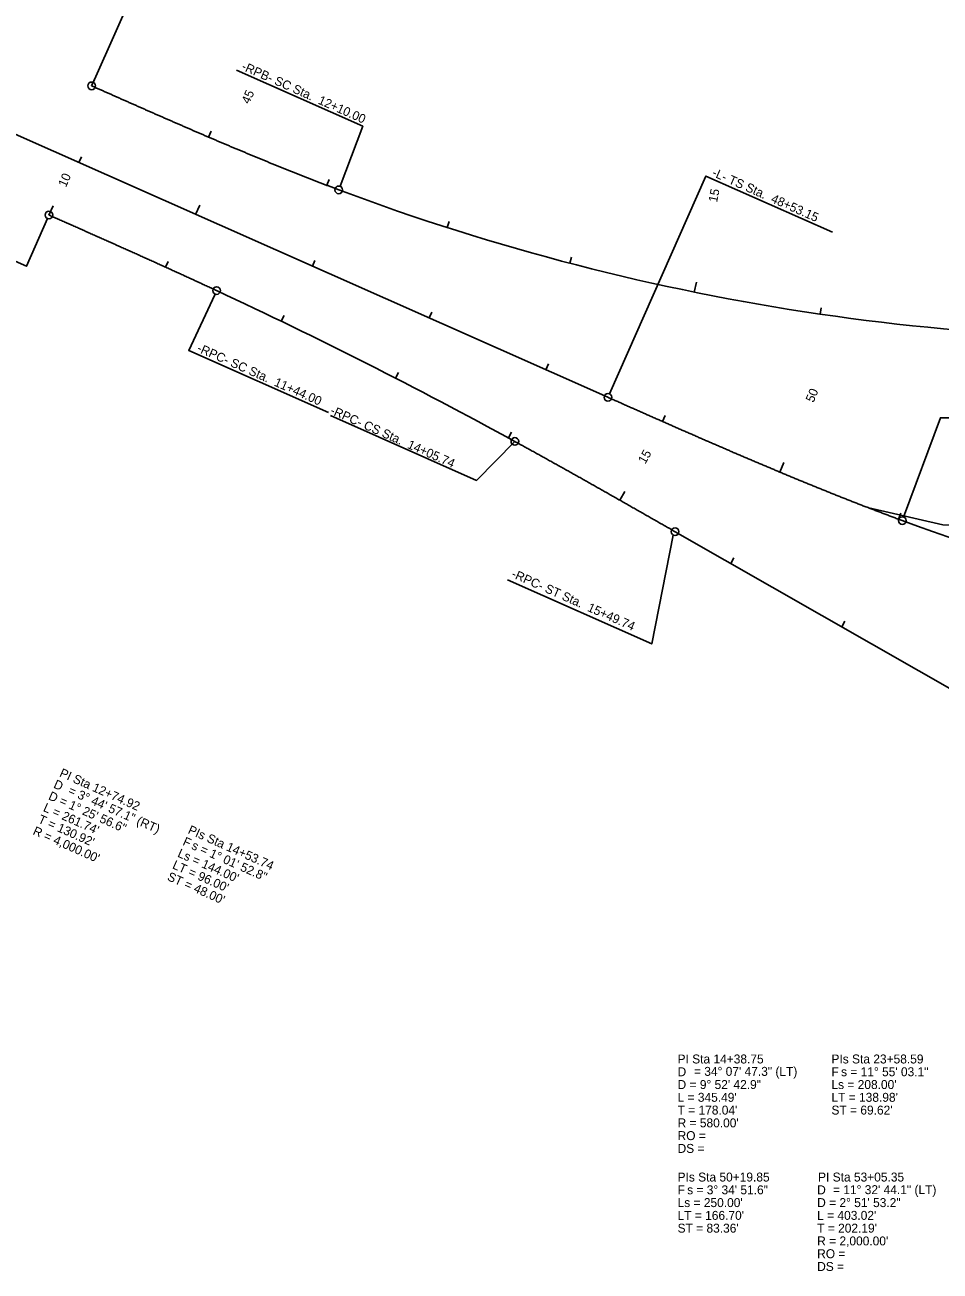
# Model space of a CAD drawing. Extents: x 1636713 to 1642783, y 841520 to 844371.
# Drawn here: x 1639901 to 1640618, y 841942 to 842918 of the extents above; entities that cross this region are included whole.
import ezdxf

# ---------------------------------------------------------------- set-up
doc = ezdxf.new("R2010")
doc.units = 0
for name, color, linetype in [('Prop Horizontal Alignment', 7, 'Continuous'), ('Prop Horizontal Alignment Curve and Spiral Data', 7, 'Continuous'), ('Prop Horizontal Alignment Station Label', 7, 'Continuous'), ('Prop Horizontal Alignment Tick Label', 7, 'Continuous'), ('Prop Horizontal Alignment Tick Large', 7, 'Continuous'), ('Prop Horizontal Alignment Tick Small', 7, 'Continuous')]:
    doc.layers.add(name, color=color, linetype=linetype)

msp = doc.modelspace()

# ---------------------------------------------------------------- linework, layer by layer
at = {"layer": 'Prop Horizontal Alignment'}
for p, q in [((1638900.9, 843272.49), (1640357.88, 842626.45)), ((1640410.49, 842521.24), (1640992.21, 842189.1)), ((1640410.49, 842521.24), (1640992.21, 842189.1))]:
    msp.add_line(p, q, dxfattribs=at)
for centre, radius, start, end in [((1640787.73, 844492.39), 1820, 249.39267, 273.94216), ((1638364.53, 839083.08), 4000, 61.30663, 65.05582), ((1638364.53, 839083.08), 4000, 61.30663, 65.05582), ((1641283.36, 844405.31), 2000, 249.66813, 261.21372)]:
    msp.add_arc(centre, radius, start, end, dxfattribs=at)
for points in [[(1639953.61, 842870.25), (1639956.21, 842869.1), (1639958.8, 842867.95), (1639961.4, 842866.8), (1639963.99, 842865.65), (1639966.58, 842864.5), (1639969.18, 842863.35), (1639971.77, 842862.2), (1639974.37, 842861.05), (1639976.96, 842859.9), (1639979.56, 842858.75), (1639982.15, 842857.61), (1639984.75, 842856.46), (1639987.35, 842855.31), (1639989.94, 842854.17), (1639992.54, 842853.02), (1639995.14, 842851.88), (1639997.73, 842850.74), (1640000.33, 842849.6), (1640002.93, 842848.45), (1640005.53, 842847.31), (1640008.13, 842846.18), (1640010.73, 842845.04), (1640013.33, 842843.9), (1640015.93, 842842.77), (1640018.53, 842841.63), (1640021.13, 842840.5), (1640023.74, 842839.37), (1640026.34, 842838.24), (1640028.94, 842837.11), (1640031.55, 842835.98), (1640034.15, 842834.86), (1640036.76, 842833.74), (1640039.37, 842832.62), (1640041.97, 842831.5), (1640044.58, 842830.38), (1640047.19, 842829.26), (1640049.8, 842828.15), (1640052.41, 842827.04), (1640055.03, 842825.93), (1640057.64, 842824.82), (1640060.25, 842823.71), (1640062.87, 842822.61), (1640065.48, 842821.51), (1640068.1, 842820.41), (1640070.72, 842819.32), (1640073.34, 842818.22), (1640075.95, 842817.13), (1640078.58, 842816.04), (1640081.2, 842814.96), (1640083.82, 842813.88), (1640086.44, 842812.79), (1640089.07, 842811.72), (1640091.7, 842810.64), (1640094.32, 842809.57), (1640096.95, 842808.5), (1640099.58, 842807.44), (1640102.22, 842806.37), (1640104.85, 842805.32), (1640107.48, 842804.26), (1640110.12, 842803.21), (1640112.75, 842802.16), (1640115.39, 842801.11), (1640118.03, 842800.07), (1640120.67, 842799.03), (1640123.31, 842797.99), (1640125.96, 842796.96), (1640128.6, 842795.93), (1640131.25, 842794.91), (1640133.9, 842793.89), (1640136.55, 842792.87), (1640139.2, 842791.86), (1640141.85, 842790.85), (1640144.5, 842789.85), (1640147.16, 842788.84)], [(1639920.18, 842769.12), (1639921.96, 842768.33), (1639923.74, 842767.54), (1639925.52, 842766.75), (1639927.3, 842765.96), (1639929.08, 842765.17), (1639930.86, 842764.38), (1639932.64, 842763.6), (1639934.41, 842762.81), (1639936.19, 842762.02), (1639937.97, 842761.23), (1639939.75, 842760.44), (1639941.53, 842759.65), (1639943.31, 842758.86), (1639945.09, 842758.07), (1639946.86, 842757.28), (1639948.64, 842756.49), (1639950.42, 842755.7), (1639952.2, 842754.91), (1639953.98, 842754.12), (1639955.75, 842753.33), (1639957.53, 842752.53), (1639959.31, 842751.74), (1639961.09, 842750.95), (1639962.87, 842750.16), (1639964.64, 842749.37), (1639966.42, 842748.57), (1639968.2, 842747.78), (1639969.97, 842746.99), (1639971.75, 842746.2), (1639973.53, 842745.4), (1639975.3, 842744.61), (1639977.08, 842743.81), (1639978.86, 842743.02), (1639980.63, 842742.22), (1639982.41, 842741.43), (1639984.18, 842740.63), (1639985.96, 842739.83), (1639987.73, 842739.04), (1639989.51, 842738.24), (1639991.28, 842737.44), (1639993.06, 842736.64), (1639994.83, 842735.84), (1639996.61, 842735.04), (1639998.38, 842734.25), (1640000.16, 842733.44), (1640001.93, 842732.64), (1640003.7, 842731.84), (1640005.48, 842731.04), (1640007.25, 842730.24), (1640009.02, 842729.43), (1640010.79, 842728.63), (1640012.56, 842727.83), (1640014.34, 842727.02), (1640016.11, 842726.22), (1640017.88, 842725.41), (1640019.65, 842724.6), (1640021.42, 842723.8), (1640023.19, 842722.99), (1640024.96, 842722.18), (1640026.73, 842721.37), (1640028.5, 842720.56), (1640030.27, 842719.75), (1640032.04, 842718.94), (1640033.81, 842718.13), (1640035.57, 842717.31), (1640037.34, 842716.5), (1640039.11, 842715.68), (1640040.87, 842714.87), (1640042.64, 842714.05), (1640044.41, 842713.24), (1640046.17, 842712.42), (1640047.94, 842711.6), (1640049.7, 842710.78), (1640051.47, 842709.96)], [(1639920.18, 842769.12), (1639921.96, 842768.33), (1639923.74, 842767.54), (1639925.52, 842766.75), (1639927.3, 842765.96), (1639929.08, 842765.17), (1639930.86, 842764.38), (1639932.64, 842763.6), (1639934.41, 842762.81), (1639936.19, 842762.02), (1639937.97, 842761.23), (1639939.75, 842760.44), (1639941.53, 842759.65), (1639943.31, 842758.86), (1639945.09, 842758.07), (1639946.86, 842757.28), (1639948.64, 842756.49), (1639950.42, 842755.7), (1639952.2, 842754.91), (1639953.98, 842754.12), (1639955.75, 842753.33), (1639957.53, 842752.53), (1639959.31, 842751.74), (1639961.09, 842750.95), (1639962.87, 842750.16), (1639964.64, 842749.37), (1639966.42, 842748.57), (1639968.2, 842747.78), (1639969.97, 842746.99), (1639971.75, 842746.2), (1639973.53, 842745.4), (1639975.3, 842744.61), (1639977.08, 842743.81), (1639978.86, 842743.02), (1639980.63, 842742.22), (1639982.41, 842741.43), (1639984.18, 842740.63), (1639985.96, 842739.83), (1639987.73, 842739.04), (1639989.51, 842738.24), (1639991.28, 842737.44), (1639993.06, 842736.64), (1639994.83, 842735.84), (1639996.61, 842735.04), (1639998.38, 842734.25), (1640000.16, 842733.44), (1640001.93, 842732.64), (1640003.7, 842731.84), (1640005.48, 842731.04), (1640007.25, 842730.24), (1640009.02, 842729.43), (1640010.79, 842728.63), (1640012.56, 842727.83), (1640014.34, 842727.02), (1640016.11, 842726.22), (1640017.88, 842725.41), (1640019.65, 842724.6), (1640021.42, 842723.8), (1640023.19, 842722.99), (1640024.96, 842722.18), (1640026.73, 842721.37), (1640028.5, 842720.56), (1640030.27, 842719.75), (1640032.04, 842718.94), (1640033.81, 842718.13), (1640035.57, 842717.31), (1640037.34, 842716.5), (1640039.11, 842715.68), (1640040.87, 842714.87), (1640042.64, 842714.05), (1640044.41, 842713.24), (1640046.17, 842712.42), (1640047.94, 842711.6), (1640049.7, 842710.78), (1640051.47, 842709.96)], [(1640357.88, 842626.45), (1640360.97, 842625.08), (1640364.06, 842623.71), (1640367.14, 842622.35), (1640370.23, 842620.98), (1640373.32, 842619.61), (1640376.41, 842618.24), (1640379.5, 842616.87), (1640382.59, 842615.5), (1640385.68, 842614.14), (1640388.77, 842612.77), (1640391.86, 842611.41), (1640394.95, 842610.04), (1640398.04, 842608.68), (1640401.13, 842607.31), (1640404.22, 842605.95), (1640407.31, 842604.59), (1640410.41, 842603.23), (1640413.5, 842601.87), (1640416.59, 842600.51), (1640419.69, 842599.16), (1640422.78, 842597.8), (1640425.88, 842596.45), (1640428.97, 842595.1), (1640432.07, 842593.75), (1640435.17, 842592.4), (1640438.27, 842591.06), (1640441.37, 842589.71), (1640444.47, 842588.37), (1640447.57, 842587.03), (1640450.67, 842585.69), (1640453.77, 842584.35), (1640456.88, 842583.02), (1640459.98, 842581.69), (1640463.09, 842580.36), (1640466.19, 842579.03), (1640469.3, 842577.7), (1640472.41, 842576.38), (1640475.52, 842575.06), (1640478.63, 842573.74), (1640481.74, 842572.43), (1640484.86, 842571.12), (1640487.97, 842569.81), (1640491.09, 842568.51), (1640494.21, 842567.2), (1640497.32, 842565.9), (1640500.44, 842564.61), (1640503.56, 842563.31), (1640506.69, 842562.03), (1640509.81, 842560.74), (1640512.94, 842559.46), (1640516.06, 842558.18), (1640519.19, 842556.9), (1640522.32, 842555.63), (1640525.45, 842554.36), (1640528.59, 842553.1), (1640531.72, 842551.84), (1640534.86, 842550.58), (1640538, 842549.33), (1640541.13, 842548.08), (1640544.28, 842546.84), (1640547.42, 842545.6), (1640550.56, 842544.37), (1640553.71, 842543.14), (1640556.86, 842541.91), (1640560.01, 842540.69), (1640563.16, 842539.47), (1640566.31, 842538.26), (1640569.47, 842537.05), (1640572.63, 842535.85), (1640575.79, 842534.65), (1640578.95, 842533.46), (1640582.11, 842532.27), (1640585.27, 842531.09), (1640588.44, 842529.92)], [(1640410.49, 842521.24), (1640408.8, 842522.21), (1640407.11, 842523.17), (1640405.42, 842524.14), (1640403.73, 842525.1), (1640402.04, 842526.07), (1640400.35, 842527.03), (1640398.66, 842528), (1640396.97, 842528.96), (1640395.28, 842529.93), (1640393.59, 842530.89), (1640391.9, 842531.85), (1640390.21, 842532.82), (1640388.52, 842533.78), (1640386.83, 842534.75), (1640385.14, 842535.71), (1640383.45, 842536.67), (1640381.76, 842537.64), (1640380.07, 842538.6), (1640378.38, 842539.56), (1640376.69, 842540.53), (1640374.99, 842541.49), (1640373.3, 842542.45), (1640371.61, 842543.41), (1640369.92, 842544.37), (1640368.23, 842545.34), (1640366.54, 842546.3), (1640364.84, 842547.26), (1640363.15, 842548.22), (1640361.46, 842549.18), (1640359.77, 842550.14), (1640358.07, 842551.1), (1640356.38, 842552.06), (1640354.69, 842553.02), (1640352.99, 842553.98), (1640351.3, 842554.93), (1640349.61, 842555.89), (1640347.91, 842556.85), (1640346.22, 842557.81), (1640344.52, 842558.76), (1640342.83, 842559.72), (1640341.13, 842560.67), (1640339.44, 842561.63), (1640337.74, 842562.58), (1640336.05, 842563.54), (1640334.35, 842564.49), (1640332.65, 842565.45), (1640330.96, 842566.4), (1640329.26, 842567.35), (1640327.56, 842568.3), (1640325.87, 842569.25), (1640324.17, 842570.21), (1640322.47, 842571.16), (1640320.77, 842572.1), (1640319.07, 842573.05), (1640317.37, 842574), (1640315.67, 842574.95), (1640313.97, 842575.9), (1640312.27, 842576.84), (1640310.57, 842577.79), (1640308.87, 842578.73), (1640307.17, 842579.68), (1640305.47, 842580.62), (1640303.77, 842581.57), (1640302.06, 842582.51), (1640300.36, 842583.45), (1640298.66, 842584.39), (1640296.95, 842585.33), (1640295.25, 842586.27), (1640293.54, 842587.21), (1640291.84, 842588.15), (1640290.13, 842589.08), (1640288.43, 842590.02), (1640286.72, 842590.96), (1640285.02, 842591.89)], [(1640410.49, 842521.24), (1640408.8, 842522.21), (1640407.11, 842523.17), (1640405.42, 842524.14), (1640403.73, 842525.1), (1640402.04, 842526.07), (1640400.35, 842527.03), (1640398.66, 842528), (1640396.97, 842528.96), (1640395.28, 842529.93), (1640393.59, 842530.89), (1640391.9, 842531.85), (1640390.21, 842532.82), (1640388.52, 842533.78), (1640386.83, 842534.75), (1640385.14, 842535.71), (1640383.45, 842536.67), (1640381.76, 842537.64), (1640380.07, 842538.6), (1640378.38, 842539.56), (1640376.69, 842540.53), (1640374.99, 842541.49), (1640373.3, 842542.45), (1640371.61, 842543.41), (1640369.92, 842544.37), (1640368.23, 842545.34), (1640366.54, 842546.3), (1640364.84, 842547.26), (1640363.15, 842548.22), (1640361.46, 842549.18), (1640359.77, 842550.14), (1640358.07, 842551.1), (1640356.38, 842552.06), (1640354.69, 842553.02), (1640352.99, 842553.98), (1640351.3, 842554.93), (1640349.61, 842555.89), (1640347.91, 842556.85), (1640346.22, 842557.81), (1640344.52, 842558.76), (1640342.83, 842559.72), (1640341.13, 842560.67), (1640339.44, 842561.63), (1640337.74, 842562.58), (1640336.05, 842563.54), (1640334.35, 842564.49), (1640332.65, 842565.45), (1640330.96, 842566.4), (1640329.26, 842567.35), (1640327.56, 842568.3), (1640325.87, 842569.25), (1640324.17, 842570.21), (1640322.47, 842571.16), (1640320.77, 842572.1), (1640319.07, 842573.05), (1640317.37, 842574), (1640315.67, 842574.95), (1640313.97, 842575.9), (1640312.27, 842576.84), (1640310.57, 842577.79), (1640308.87, 842578.73), (1640307.17, 842579.68), (1640305.47, 842580.62), (1640303.77, 842581.57), (1640302.06, 842582.51), (1640300.36, 842583.45), (1640298.66, 842584.39), (1640296.95, 842585.33), (1640295.25, 842586.27), (1640293.54, 842587.21), (1640291.84, 842588.15), (1640290.13, 842589.08), (1640288.43, 842590.02), (1640286.72, 842590.96), (1640285.02, 842591.89)]]:
    msp.add_spline(points, degree=3, dxfattribs=at)
at = {"layer": 'Prop Horizontal Alignment Station Label'}
for points in [[(1639866.6, 843006.4), (1639989.77, 842951.79), (1639954.84, 842872.99)], [(1640148.22, 842791.65), (1640165.86, 842838.58), (1640067, 842882.42)], [(1640359.09, 842629.2), (1640434.65, 842799.59), (1640533.84, 842755.6)], [(1639765.22, 842789.98), (1639902.6, 842729.07), (1639918.97, 842766.37)], [(1640049.97, 842706.73), (1640029.62, 842662.98), (1640139.12, 842614.43)], [(1640285.02, 842591.89), (1640254.99, 842561.44), (1640140.64, 842612.15)], [(1640589.49, 842532.73), (1640618.29, 842610.47), (1640722.12, 842610.47)], [(1640778.33, 842524.61), (1640620.11, 842526.65), (1640562.11, 842539.88)], [(1640409, 842518.64), (1640392.19, 842433.46), (1640279.34, 842483.49)]]:
    msp.add_lwpolyline(points, dxfattribs=at)
for centre in [(1639953.61, 842870.25), (1640147.16, 842788.84), (1639920.18, 842769.12), (1640051.47, 842709.96), (1640357.88, 842626.45), (1640285.02, 842591.89), (1640588.44, 842529.92), (1640410.49, 842521.24)]:
    msp.add_circle(centre, 3, dxfattribs=at)
at = {"layer": 'Prop Horizontal Alignment Tick Large'}
for p, q in [((1639953.61, 842870.25), (1639956.86, 842877.56)), ((1639920.18, 842769.12), (1639923.43, 842776.43)), ((1640035.04, 842769.6), (1640038.28, 842776.92)), ((1640425.57, 842708.79), (1640427.16, 842716.63)), ((1640492.54, 842567.9), (1640495.63, 842575.28)), ((1640367.28, 842545.88), (1640371.23, 842552.83))]:
    msp.add_line(p, q, dxfattribs=at)
at = {"layer": 'Prop Horizontal Alignment Tick Small'}
for p, q in [((1640045.2, 842830.11), (1640047.17, 842834.71)), ((1639943.62, 842810.14), (1639945.65, 842814.71)), ((1640137.81, 842792.39), (1640139.59, 842797.06)), ((1640232.15, 842759.26), (1640233.68, 842764.02)), ((1640328.17, 842731.37), (1640329.43, 842736.21)), ((1640011.48, 842728.32), (1640013.55, 842732.87)), ((1640126.46, 842729.07), (1640128.48, 842733.64)), ((1640524.07, 842691.59), (1640524.79, 842696.54)), ((1640524.08, 842691.59), (1640524.8, 842696.54)), ((1640102.08, 842685.99), (1640104.25, 842690.49)), ((1640217.87, 842688.53), (1640219.9, 842693.1)), ((1640309.29, 842648), (1640311.32, 842652.57)), ((1640191.6, 842641.43), (1640193.88, 842645.88)), ((1640400.72, 842607.5), (1640402.74, 842612.07)), ((1640279.98, 842594.64), (1640282.37, 842599.03)), ((1640585.49, 842531.01), (1640587.23, 842535.7)), ((1640454.14, 842496.32), (1640456.62, 842500.67)), ((1640540.98, 842446.74), (1640543.46, 842451.08))]:
    msp.add_line(p, q, dxfattribs=at)

# ---------------------------------------------------------------- texts
at = {"layer": 'Prop Horizontal Alignment Curve and Spiral Data'}
for s, p in [('PI Sta 12+74.92', (1639927.87, 842329.91)), ('D', (1639923.2, 842321.04)), ('D = 1%%d 25\' 56.6"', (1639919.15, 842311.9)), ('= 3%%d 44\' 57.1" (RT)', (1639934.59, 842316.12)), ("L = 261.74'", (1639915.1, 842302.76)), ("T = 130.92'", (1639911.04, 842293.62)), ("R = 4,000.00'", (1639906.99, 842284.48)), ('PIs Sta 14+53.74', (1640028.43, 842285.32)), ('F', (1640024.38, 842276.18)), ('s = 1%%d 01\' 52.8"', (1640031.25, 842273.13)), ("Ls = 144.00'", (1640020.32, 842267.04)), ("LT = 96.00'", (1640016.27, 842257.9)), ("ST = 48.00'", (1640012.22, 842248.76))]:
    msp.add_text(s, height=7, rotation=336.08714, dxfattribs=at).set_placement(p)
for s, p in [('PI Sta 14+38.75', (1640412.46, 842104.99)), ('PIs Sta 23+58.59', (1640532.96, 842104.99)), ('D', (1640412.46, 842094.99)), ('= 34%%d 07\' 47.3" (LT)', (1640425.31, 842095.29)), ('F', (1640532.96, 842094.99)), ('s = 11%%d 55\' 03.1"', (1640540.48, 842094.99)), ('D = 9%%d 52\' 42.9"', (1640412.46, 842084.99)), ("Ls = 208.00'", (1640532.96, 842084.99)), ("L = 345.49'", (1640412.46, 842074.99)), ("LT = 138.98'", (1640532.96, 842074.99)), ("T = 178.04'", (1640412.46, 842064.99)), ("ST = 69.62'", (1640532.96, 842064.99)), ("R = 580.00'", (1640412.46, 842054.99)), ('RO = ', (1640412.46, 842044.99)), ('DS =', (1640412.46, 842034.99)), ('PIs Sta 50+19.85', (1640412.46, 842012.57)), ('PI Sta 53+05.35', (1640522.46, 842012.57)), ('F', (1640412.46, 842002.57)), ('s = 3%%d 34\' 51.6"', (1640419.97, 842002.57)), ('D', (1640521.78, 842002.57)), ('= 11%%d 32\' 44.1" (LT)', (1640534.19, 842002.69)), ("Ls = 250.00'", (1640412.46, 841992.57)), ('D = 2%%d 51\' 53.2"', (1640521.78, 841992.57)), ("LT = 166.70'", (1640412.46, 841982.57)), ("L = 403.02'", (1640521.78, 841982.57)), ("ST = 83.36'", (1640412.46, 841972.57)), ("T = 202.19'", (1640521.78, 841972.57)), ("R = 2,000.00'", (1640521.78, 841962.57)), ('RO = ', (1640521.78, 841952.57)), ('DS =', (1640521.78, 841942.57))]:
    msp.add_text(s, height=7, dxfattribs=at).set_placement(p)
at = {"layer": 'Prop Horizontal Alignment Station Label'}
for s, p in [('-RPB- SC Sta.  12+10.00', (1640070.43, 842883.08)), ('-L- TS Sta.  48+53.15', (1640438.88, 842799.9)), ('-RPC- SC Sta.  11+44.00', (1640035.52, 842662.55)), ('-RPC- CS Sta.  14+05.74', (1640139.85, 842613.74)), ('-RPC- ST Sta.  15+49.74', (1640281.82, 842485.79))]:
    msp.add_text(s, height=7, rotation=336.08714, dxfattribs=at).set_placement(p)
at = {"layer": 'Prop Horizontal Alignment Tick Label'}
for s, rotation, p in [('45', 66.08714, (1640076.97, 842855.52)), ('10', 66.08714, (1639933.46, 842790.39)), ('15', 78.52221, (1640443.35, 842778.71)), ('50', 67.32267, (1640518.9, 842621.9)), ('15', 60.39837, (1640387.15, 842573.76))]:
    msp.add_text(s, height=7, rotation=rotation, dxfattribs=at).set_placement(p)

doc.saveas('drawing.dxf')
